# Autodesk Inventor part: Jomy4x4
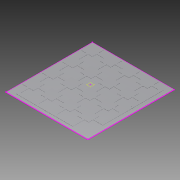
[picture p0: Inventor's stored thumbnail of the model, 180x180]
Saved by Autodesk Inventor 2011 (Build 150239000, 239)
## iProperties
Created: 2014-04
Part Number: Jomy4x4
Document SubType Name: Modeling
Designer: Evgeny
Density: 1 g/cm^3
Author: Evgeny
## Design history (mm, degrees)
sketch "Эскиз1"
  geometry: L1 (-20.75, 60.5)-(20.75, 60.5); L2 (20.75, 48.5)-(-20.75, 48.5); L3 (-45, 24.25)-(-45, -24.25); L4 (-57, -24.25)-(-57, 24.25); L5 (45, -24.25)-(45, 24.25); L6 (81.25, 60.5)-(122.75, 60.5); L7 (122.75, 48.5)-(81.25, 48.5); L8 (57, 24.25)-(57, -24.25); L9 (147, -24.25)-(147, 24.25); L10 (183.25, 60.5)-(220.75, 60.5); L11 (220.75, 48.5)-(183.25, 48.5); L12 (159, 24.25)-(159, -24.25); L13 (-159, -24.25)-(-159, 24.25); L14 (-183.25, 24.25)-(-183.25, 84.75); L15 (-122.75, 60.5)-(-81.25, 60.5); L16 (-81.25, 48.5)-(-122.75, 48.5); L17 (-147, 24.25)-(-147, -24.25); L18 (-159, -133.25)-(-159, -84.75); L19 (-183.25, -84.75)-(-183.25, -24.25); L20 (-122.75, -48.5)-(-81.25, -48.5); L21 (-81.25, -60.5)-(-122.75, -60.5); L22 (-147, -84.75)-(-147, -133.25); L23 (-57, -133.25)-(-57, -84.75); L24 (-20.75, -48.5)-(20.75, -48.5); L25 (20.75, -60.5)-(-20.75, -60.5); L26 (-45, -84.75)-(-45, -133.25); L27 (45, -133.25)-(45, -84.75); L28 (81.25, -48.5)-(122.75, -48.5); L29 (122.75, -60.5)-(81.25, -60.5); L30 (57, -84.75)-(57, -133.25); L31 (147, -133.25)-(147, -84.75); L32 (183.25, -48.5)-(220.75, -48.5); L33 (220.75, -60.5)-(183.25, -60.5); L34 (159, -84.75)-(159, -133.25); L35 (-159, -242.25)-(-159, -193.75); L36 (-183.25, -193.75)-(-183.25, -133.25); L37 (-122.75, -157.5)-(-81.25, -157.5); L38 (-81.25, -169.5)-(-122.75, -169.5); L39 (-147, -193.75)-(-147, -242.25); L40 (-57, -242.25)-(-57, -193.75); L41 (-20.75, -157.5)-(20.75, -157.5); L42 (20.75, -169.5)-(-20.75, -169.5); L43 (-45, -193.75)-(-45, -242.25); L44 (45, -242.25)-(45, -193.75); L45 (81.25, -157.5)-(122.75, -157.5); L46 (122.75, -169.5)-(81.25, -169.5); L47 (57, -193.75)-(57, -241.25); L48 (147, -241.25)-(147, -193.75); L49 (183.25, -156.5)-(220.75, -156.5); L50 (224.75, -168.5)-(183.25, -168.5); L51 (159, -192.75)-(159, -241.25); L52 (-159, 84.75)-(-159, 133.25); L53 (-183.25, 193.75)-(-122.75, 193.75); L54 (-183.25, 133.25)-(-183.25, 193.75); L55 (-122.75, 169.5)-(-81.25, 169.5); L56 (-81.25, 157.5)-(-122.75, 157.5); L57 (-147, 133.25)-(-147, 84.75); L58 (-57, 84.75)-(-57, 133.25); L59 (-81.25, 193.75)-(-20.75, 193.75); L60 (-20.75, 169.5)-(20.75, 169.5); L61 (20.75, 157.5)-(-20.75, 157.5); L62 (-45, 133.25)-(-45, 84.75); L63 (45, 84.75)-(45, 133.25); L64 (20.75, 193.75)-(81.25, 193.75)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; 1 further point
  constraints: 392 end point, 152 parallel, 66 collinear, 60 perpendicular, 48 horizontal, 2 point on line
  dimensions: "d4" = 12 distance between parallel lines of L2 L1; "d6" = 12 distance between parallel lines of L3 L4; "d12" = 12 distance between parallel lines of L7 L6; "d14" = 12 distance between parallel lines of L8 L5; "d20" = 12 distance between parallel lines of L11 L10; "d22" = 12 distance between parallel lines of L12 L9; "d28" = 12 distance between parallel lines of L16 L15; "d30" = 12 distance between parallel lines of L17 L13; "d36" = 12 distance between parallel lines of L21 L20; "d38" = 12 distance between parallel lines of L22 L18; "d44" = 12 distance between parallel lines of L25 L24; "d46" = 12 distance between parallel lines of L26 L23; "d52" = 12 distance between parallel lines of L29 L28; "d54" = 12 distance between parallel lines of L30 L27; "d60" = 12 distance between parallel lines of L33 L32; "d62" = 12 distance between parallel lines of L34 L31; "d68" = 12 distance between parallel lines of L38 L37; "d70" = 12 distance between parallel lines of L39 L35; "d76" = 12 distance between parallel lines of L42 L41; "d78" = 12 distance between parallel lines of L43 L40; "d84" = 12 distance between parallel lines of L46 L45; "d86" = 12 distance between parallel lines of L47 L44; "d92" = 12 distance between parallel lines of L50 L49; "d94" = 12 distance between parallel lines of L51 L48; "d100" = 12 distance between parallel lines of L56 L55; "d102" = 12 distance between parallel lines of L57 L52; "d104" = 24.25 distance between parallel lines of L55 L53; "d108" = 12 distance between parallel lines of L61 L60; "d110" = 12 distance between parallel lines of L62 L58; "d112" = 24.25 distance between parallel lines of L60 L59; "d116" = 12 distance between parallel lines of L66 L65; "d118" = 12 distance between parallel lines of L67 L63; "d120" = 24.25 distance between parallel lines of L65 L64; "d124" = 12 distance between parallel lines of L71 L70; "d126" = 12 distance between parallel lines of L72 L68; "d128" = 24.25 distance between parallel lines of L70 L69; "d146" = 60.5 distance between parallel lines of L80 L53; "d147" = 60.5 distance between parallel lines of L95 L54; "d148" = 48.5 distance between parallel lines of L81 L80; "d149" = 41.5 distance between parallel lines of L98 L95; "d159" = 63.5 distance between parallel lines of L77 L179; "d160" = 48.5 distance between parallel lines of L188 L178; "d161" = 53.5 distance between parallel lines of L165 L74; "d162" = 16 distance between parallel lines of L74 L142; "d163" = 16 distance between parallel lines of L186 L77
extrude "Выдавливание1" new body sketch "Эскиз1" distance "d150" = 1; taper "d151" = 0 deg
sketch "Эскиз2"
  geometry: L1 (169.5, 0)-(-168.5, 0) reference; 2 further points
  dimensions: "d152" = 7 distance from line of point (0, -7) L1
node "РабПлоскость1"
sketch "Эскиз3"
  geometry: L1 (-200, 210)-(255, 210); L2 (255, 210)-(255, -270); L3 (255, -270)-(-200, -270); L4 (-200, -270)-(-200, 210); C1 r 4.5 at (229, 0); C2 r 4.5 at (0, -249.45); 1 further point
  constraints: 8 end point, 2 centre point, 2 parallel, 1 horizontal, 1 perpendicular
  dimensions: "d153" = 455 distance between parallel lines of L2 L4; "d154" = 480 distance between parallel lines of L3 L1; "d155" = 255 distance from line of L2 point (0, 0); "d156" = 210 distance from line of L1 point (0, 0); "d170" = 9 diameter of C2; "d171" = 9 diameter of C1
node "РабПлоскость2"
sketch "Эскиз6"
  geometry: L1 (-200, 210)-(255, 210) reference; L2 (-200, -270)-(-200, 210) reference; L3 (255, -270)-(-200, -270) reference; L4 (255, 210)-(255, -270) reference; 1 further point
extrude "Выдавливание6" join sketch "Эскиз3" distance "d198" = 1; taper "d199" = 0 deg
sketch "Эскиз7"
  geometry: L1 (159, -257.25)-(-159, -257.25) reference; L2 (236.75, 169.5)-(236.75, -168.5) reference; C1 r 1.5 at (0, -249.25); C2 r 1.5 at (228.75, 0); 1 further point
  constraints: 2 centre point
  dimensions: "d200" = 3 diameter of C2; "d201" = 3 diameter of C1; "d202" = 8 distance from line of L1 C1.centre; "d203" = 8 distance from line of L2 C2.centre
extrude "Выдавливание8" cut sketch "Эскиз7" distance "d206" = 10; taper "d207" = 0 deg
node "Твердое тело1"
other parameters: "d0" = 60.5, "d1" = 60.5, "d2" = 20.75, "d3" = 24.25, "d5" = 41.5, "d7" = 48.5, "d8" = 24.25, "d9" = 24.25, "d10" = 60.5, "d11" = 60.5, "d13" = 41.5, "d15" = 48.5, "d16" = 24.25, "d17" = 24.25, "d18" = 60.5, "d19" = 60.5, "d21" = 41.5, "d23" = 48.5, "d24" = 24.25, "d25" = 24.25, "d26" = 60.5, "d27" = 60.5, "d29" = 41.5, "d31" = 48.5, "d32" = 24.25, "d33" = 24.25, "d34" = 60.5, "d35" = 60.5, "d39" = 48.5, "d40" = 24.25, "d41" = 24.25, "d42" = 60.5, "d43" = 60.5, "d47" = 48.5, "d48" = 24.25, "d49" = 24.25, "d50" = 60.5, "d51" = 60.5, "d55" = 48.5, "d56" = 24.25, "d57" = 24.25, "d58" = 60.5, "d59" = 60.5, "d61" = 41.5, "d63" = 48.5, "d64" = 24.25, "d65" = 24.25, "d66" = 60.5, "d67" = 60.5, "d71" = 48.5, "d72" = 24.25, "d73" = 24.25, "d74" = 60.5, "d75" = 60.5, "d79" = 48.5, "d80" = 24.25, "d81" = 24.25, "d82" = 60.5, "d83" = 60.5, "d87" = 48.5, "d88" = 24.25, "d89" = 24.25, "d90" = 60.5, "d91" = 60.5, "d95" = 48.5, "d96" = 24.25, "d97" = 24.25, "d98" = 60.5, "d99" = 60.5, "d101" = 41.5, "d103" = 48.5, "d105" = 24.25, "d106" = 60.5, "d107" = 60.5, "d109" = 41.5, "d111" = 48.5, "d113" = 24.25, "d114" = 60.5, "d115" = 60.5, "d117" = 41.5, "d119" = 48.5, "d121" = 24.25, "d122" = 60.5, "d123" = 60.5, "d125" = 41.5, "d127" = 48.5, "d129" = 24.25, "d130" = 48.5, "d131" = 41.5, "d132" = 24.25, "d133" = 41.5, "d135" = 48.5, "d136" = 41.5, "d137" = 41.5, "d138" = 41.5, "d139" = 41.5, "d140" = 24.25, "d141" = 48.5, "d142" = 48.5, "d143" = 48.5, "d144" = 16, "d145" = 16
